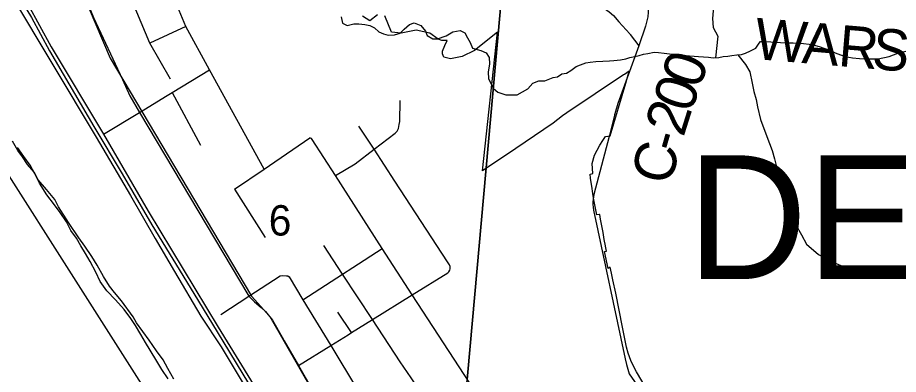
# Model space of a CAD drawing. Extents: x 0 to 43.4, y -8.1 to 22.
# Drawn here: x 3.073 to 4.286, y 17.149 to 17.64 of the extents above; entities that cross this region are included whole.
import ezdxf

# ---------------------------------------------------------------- set-up
doc = ezdxf.new("R2010")
doc.units = 0
for name, color, linetype in [('GM_X_City_Street', 7, 'Continuous'), ('GM_X_Corporation', 7, 'Continuous'), ('GM_X_County_Road', 7, 'Continuous'), ('GM_X_County_Road_Text', 7, 'Continuous'), ('GM_X_Major_River', 7, 'Continuous'), ('GM_X_Minor_River', 7, 'Continuous'), ('GM_X_Rail_Line', 7, 'Continuous'), ('GM_X_Section_Text', 7, 'Continuous'), ('GM_X_Township_Text', 7, 'Continuous'), ('GM_X_US_Route', 7, 'Continuous')]:
    doc.layers.add(name, color=color, linetype=linetype)

msp = doc.modelspace()

# ---------------------------------------------------------------- linework, layer by layer
at = {"layer": 'GM_X_City_Street'}
for p, q in [((3.305, 17.6279), (3.2551, 17.6051)), ((3.286, 17.537), (3.3248, 17.4648)), ((3.3718, 17.4041), (3.4138, 17.3377)), ((3.533, 17.2066), (3.5141, 17.2345))]:
    msp.add_line(p, q, dxfattribs=at)
for points in [[(3.4124, 17.4317), (3.3376, 17.5683), (3.305, 17.6279), (3.2819, 17.6838), (3.2006, 17.8528)], [(3.2836, 17.5556), (3.2551, 17.6051), (3.2315, 17.6623)], [(3.1915, 17.4797), (3.2411, 17.5098), (3.2792, 17.5329), (3.286, 17.537), (3.3376, 17.5683)], [(3.5106, 17.423), (3.538, 17.4391), (3.5639, 17.459), (3.593, 17.4813), (3.5956, 17.4841), (3.5973, 17.4878), (3.5986, 17.4931), (3.5992, 17.4975), (3.5998, 17.5263)], [(3.6688, 17.2965), (3.6685, 17.2977), (3.6675, 17.2999), (3.6651, 17.3041), (3.5926, 17.4152), (3.5639, 17.459), (3.5431, 17.4909)], [(3.3718, 17.4041), (3.4124, 17.4317), (3.4198, 17.4367), (3.4757, 17.4747)], [(3.9415, 16.771), (3.8933, 16.8417), (3.8772, 16.8653), (3.8669, 16.8804), (3.8199, 16.9493), (3.7756, 17.0142), (3.7168, 17.1043), (3.6955, 17.1369), (3.6162, 17.2584), (3.5751, 17.3225), (3.5106, 17.423), (3.4787, 17.4727), (3.4776, 17.4739), (3.4757, 17.4747)], [(3.684, 17.0403), (3.6667, 17.0663), (3.6417, 17.1037), (3.6148, 17.1441), (3.5998, 17.1665), (3.5617, 17.2245), (3.5205, 17.2872), (3.4947, 17.3265)], [(3.466, 17.2519), (3.5205, 17.2872), (3.5345, 17.2963), (3.5751, 17.3225)], [(3.4599, 17.1611), (3.5042, 17.1887), (3.5281, 17.2036), (3.533, 17.2066), (3.5617, 17.2245), (3.6162, 17.2584), (3.6653, 17.289), (3.6669, 17.2904), (3.6681, 17.2924), (3.6687, 17.2946), (3.6688, 17.2965)], [(3.3532, 17.2316), (3.3916, 17.2566), (3.4348, 17.2847), (3.4377, 17.2852), (3.4432, 17.2849)], [(3.4432, 17.2849), (3.4453, 17.2847), (3.4469, 17.2834), (3.466, 17.2519), (3.5042, 17.1887), (3.5412, 17.1277), (3.5791, 17.065), (3.5845, 17.0562), (3.6148, 17.0061), (3.6559, 16.9382), (3.6953, 16.8731), (3.7344, 16.8086)]]:
    msp.add_lwpolyline(points, dxfattribs=at)
at = {"layer": 'GM_X_Corporation'}
for points in [[(8.9, 20.9), (2.1, 20.9), (2.1, 18.7697), (2.2164, 18.6602), (2.3024, 18.5637), (2.4531, 18.3722), (2.5091, 18.2757), (2.5944, 18.1569), (2.6477, 18.0826), (2.8129, 17.7895), (2.9482, 17.5993), (3.2529, 17.1207), (3.3535, 16.9292), (3.4766, 16.7366), (3.5579, 16.6418), (3.619, 16.5459), (3.7774, 16.2543), (3.8686, 16.1561), (3.9643, 16.0791), (4.2564, 15.9373), (4.3533, 15.9108)], [(2.8521, 17.7909), (3.7435, 17.7155), (3.6418, 16.5844)], [(3.5685, 17.644), (3.5579, 17.636), (3.548, 17.6422)], [(3.9385, 17.1301), (3.925, 17.1526), (3.9219, 17.1583), (3.9171, 17.1683), (3.9138, 17.1781), (3.9115, 17.1866), (3.9059, 17.214), (3.8965, 17.2608), (3.8925, 17.2794), (3.8905, 17.2886), (3.8888, 17.2967), (3.886, 17.2949), (3.881, 17.3182), (3.884, 17.3189), (3.8825, 17.3256), (3.8824, 17.3261), (3.8808, 17.3349), (3.8791, 17.3442), (3.8774, 17.3535), (3.8757, 17.3629), (3.8746, 17.3694), (3.8743, 17.3694), (3.8706, 17.3686), (3.8665, 17.3896), (3.8652, 17.3978), (3.8641, 17.4049), (3.8618, 17.4192), (3.8614, 17.4247), (3.8651, 17.4259), (3.8641, 17.4394), (3.8671, 17.4511), (3.8748, 17.4647), (3.8788, 17.471), (3.8823, 17.4767), (3.889, 17.4777), (3.9102, 17.5501), (3.9152, 17.5667), (3.9084, 17.5621), (3.9074, 17.5614), (3.829, 17.509), (3.8233, 17.5051), (3.8102, 17.4951), (3.7588, 17.4603), (3.713, 17.4294), (3.7338, 17.6201), (3.7022, 17.595), (3.685, 17.5869), (3.6689, 17.5838), (3.6598, 17.5857), (3.6582, 17.5903), (3.658, 17.5942), (3.6615, 17.6021), (3.6646, 17.609), (3.6573, 17.6087), (3.6519, 17.6108), (3.6405, 17.6191), (3.6219, 17.6231), (3.6012, 17.6188), (3.5881, 17.6204), (3.5789, 17.6428)], [(2.9482, 17.5993), (3.2529, 17.1207)], [(2.9482, 17.5993), (3.2529, 17.1207)], [(3.2883, 17.1423), (3.2799, 17.1573), (3.2734, 17.1692), (3.2646, 17.1815), (3.2543, 17.1962), (3.2371, 17.2201), (3.2324, 17.2282), (3.2163, 17.2502), (3.2067, 17.2618), (3.1997, 17.2703), (3.1913, 17.2837), (3.1826, 17.2995), (3.1753, 17.3114), (3.1658, 17.3256), (3.1574, 17.3372), (3.1435, 17.3584), (3.1296, 17.3799), (3.1246, 17.3899), (3.1132, 17.4038), (3.1017, 17.417), (3.0959, 17.4277), (3.0867, 17.4382), (3.0798, 17.4486), (3.0735, 17.4574), (3.0663, 17.4701)]]:
    msp.add_lwpolyline(points, dxfattribs=at)
msp.add_lwpolyline([(4.7377, 17.6242), (4.6148, 16.5127), (3.671, 16.5519), (3.6538, 16.5644), (3.6462, 16.5775), (3.6418, 16.5844), (3.7435, 17.7155)], close=True, dxfattribs=at)
at = {"layer": 'GM_X_County_Road'}
for points in [[(3.112, 17.7916), (3.1305, 17.7553), (3.1449, 17.7124), (3.1653, 17.671), (3.1775, 17.6407), (3.2177, 17.5553), (3.2275, 17.5327), (3.2411, 17.5098), (3.3916, 17.2566), (3.3995, 17.2491), (3.4084, 17.2413), (3.4144, 17.2355), (3.424, 17.2239), (3.4374, 17.2005), (3.4403, 17.1954)], [(3.7924, 17.7091), (3.8007, 17.6978), (3.821, 17.6875), (3.8678, 17.6626), (3.8876, 17.6482), (3.8936, 17.6431), (3.901, 17.6346), (3.9158, 17.618)], [(3.9409, 17.6933), (3.9416, 17.6542), (3.9406, 17.6413), (3.9376, 17.6285), (3.9283, 17.6016), (3.8993, 17.522), (3.8953, 17.5077), (3.895, 17.5067)], [(3.9158, 17.618), (3.9165, 17.6172), (3.9283, 17.6016)], [(3.895, 17.5067), (3.8947, 17.5058), (3.8873, 17.4767), (3.8662, 17.3968), (3.8648, 17.3866), (3.8652, 17.3828), (3.8656, 17.3795)], [(3.8656, 17.3795), (3.8661, 17.3752), (3.9094, 17.1706), (3.9115, 17.1626), (3.915, 17.15), (3.9363, 17.1193), (3.9407, 17.113), (3.9477, 17.1015), (3.9526, 17.0854), (3.9596, 17.0599), (3.963, 17.0415), (3.9778, 16.9592), (3.9875, 16.9057), (3.9912, 16.8851)], [(3.4403, 17.1954), (3.4599, 17.1611), (3.4955, 17.099), (3.5317, 17.0357), (3.5663, 16.9762), (3.6066, 16.9068), (3.6432, 16.8438), (3.6835, 16.7745), (3.6969, 16.7515), (3.713, 16.7258), (3.7609, 16.661), (3.7657, 16.655), (3.7823, 16.6344), (3.804, 16.6055), (3.846, 16.5431), (3.887, 16.4854), (3.8904, 16.4807), (3.9025, 16.4638), (3.9229, 16.4395), (3.9444, 16.4189), (3.95, 16.4142), (3.9523, 16.4123)]]:
    msp.add_lwpolyline(points, dxfattribs=at)
at = {"layer": 'GM_X_Major_River'}
msp.add_lwpolyline([(3.2804, 17.1429), (3.2719, 17.1559), (3.2634, 17.1694), (3.2494, 17.1931), (3.2427, 17.2038), (3.2357, 17.2165), (3.229, 17.2261), (3.2201, 17.2384), (3.2078, 17.2515), (3.1959, 17.2642), (3.1869, 17.2769), (3.1807, 17.2899), (3.173, 17.3044), (3.1667, 17.3155), (3.1604, 17.3262), (3.1541, 17.3366), (3.1467, 17.3473), (3.1405, 17.3592), (3.1319, 17.3719), (3.1241, 17.3826), (3.1133, 17.3965), (3.1034, 17.4122), (3.0971, 17.4252), (3.0905, 17.4371), (3.0819, 17.4493), (3.073, 17.4616)], dxfattribs=at)
at = {"layer": 'GM_X_Minor_River'}
for points in [[(4.0741, 17.7643), (4.0698, 17.7511), (4.0666, 17.7413), (4.0636, 17.73), (4.0611, 17.7202), (4.0578, 17.71), (4.0506, 17.6961), (4.0397, 17.6831), (4.0329, 17.6703), (4.0318, 17.6594), (4.0308, 17.6495), (4.0298, 17.6393), (4.0306, 17.6267), (4.0372, 17.6148), (4.0338, 17.5852)], [(3.5187, 17.6413), (3.5204, 17.6329), (3.5269, 17.6297), (3.5361, 17.6318), (3.5429, 17.6317), (3.5513, 17.6308), (3.5582, 17.6296), (3.5646, 17.6264), (3.5706, 17.621), (3.577, 17.6178), (3.5835, 17.6162), (3.5919, 17.6168), (3.5996, 17.6189), (3.6054, 17.6245), (3.6128, 17.6309), (3.6193, 17.6334), (3.6284, 17.6294), (3.6348, 17.6217), (3.637, 17.6156), (3.6449, 17.6113), (3.651, 17.6112), (3.6633, 17.6151), (3.6722, 17.6207), (3.6825, 17.6228), (3.6886, 17.6196), (3.6927, 17.6127), (3.696, 17.6062), (3.6996, 17.5982), (3.711, 17.5949), (3.7182, 17.5917), (3.7223, 17.5856), (3.7229, 17.5768), (3.7208, 17.5651), (3.7214, 17.5567), (3.7251, 17.5487), (3.7284, 17.5429), (3.7344, 17.5375), (3.7454, 17.5342), (3.7527, 17.5341), (3.7607, 17.534), (3.768, 17.538), (3.7754, 17.5425), (3.7824, 17.5503), (3.7908, 17.5532), (3.7989, 17.5534), (3.8104, 17.5578), (3.8162, 17.5588), (3.8223, 17.5629), (3.8288, 17.5639), (3.8346, 17.5676), (3.842, 17.5732), (3.8481, 17.5754), (3.8555, 17.5783), (3.8612, 17.579), (3.8692, 17.5799), (3.8788, 17.5802), (3.888, 17.5808), (3.8941, 17.5814), (3.9033, 17.582), (3.9102, 17.5838), (3.9159, 17.5856), (3.9228, 17.587), (3.9289, 17.588), (3.9347, 17.5898), (3.9405, 17.5909), (3.9493, 17.593), (3.9554, 17.5925), (3.9634, 17.5912), (3.9706, 17.5907), (3.9771, 17.5898), (3.9843, 17.5893), (3.9981, 17.5876), (4.0045, 17.5871), (4.0106, 17.5866), (4.0171, 17.5865), (4.024, 17.586), (4.0308, 17.5851), (4.0385, 17.5853), (4.0442, 17.5867)], [(4.0442, 17.5867), (4.0507, 17.5874), (4.0565, 17.5884), (4.0634, 17.5891), (4.0695, 17.5897), (4.0753, 17.5915), (4.0822, 17.5944), (4.0895, 17.5981), (4.0938, 17.6052), (4.0956, 17.6076)], [(4.0956, 17.6076), (4.1038, 17.6074), (4.1166, 17.6064), (4.1303, 17.6056), (4.1409, 17.6058), (4.1515, 17.6051), (4.1663, 17.6032), (4.1765, 17.6007), (4.1892, 17.5958), (4.2009, 17.591), (4.2125, 17.5869), (4.2224, 17.5851), (4.2322, 17.5841), (4.2451, 17.5834), (4.2576, 17.5835), (4.2729, 17.5869), (4.2848, 17.5912), (4.2958, 17.5943)], [(4.0648, 17.5892), (4.0753, 17.5759), (4.0811, 17.5658), (4.0845, 17.5502), (4.0864, 17.5384), (4.09, 17.5276), (4.0916, 17.5173), (4.0957, 17.5002), (4.1003, 17.4875), (4.1082, 17.4672), (4.1117, 17.4572), (4.1152, 17.4457), (4.118, 17.435), (4.1207, 17.4232), (4.1252, 17.4068), (4.1291, 17.3964), (4.1326, 17.3849), (4.1383, 17.3703), (4.1444, 17.355), (4.152, 17.3411), (4.1589, 17.3284), (4.1756, 17.314), (4.1925, 17.3048), (4.2097, 17.2975), (4.2278, 17.2922), (4.2399, 17.2896), (4.2501, 17.2889), (4.2619, 17.2879), (4.2721, 17.2865), (4.2868, 17.2816)]]:
    msp.add_lwpolyline(points, dxfattribs=at)
at = {"layer": 'GM_X_Rail_Line'}
for points in [[(2.1, 18.9805), (2.1848, 18.9497), (2.3592, 18.8383), (2.5014, 18.7512), (2.6158, 18.6907), (2.7269, 18.6311), (2.7893, 18.6123), (2.8663, 18.5659), (2.9659, 18.5014), (3.0581, 18.4348), (3.118, 18.3921), (3.1299, 18.3321), (3.1312, 18.287), (3.0912, 18.2087), (3.028, 18.1378), (3.0132, 18.0857), (3.0138, 18.043), (3.0154, 18.0122), (3.102, 17.8166), (3.2006, 17.5844), (3.3952, 17.2569), (3.4206, 17.2288), (3.4993, 17.0909)], [(2.4533, 18.5052), (2.6298, 18.3221), (2.6528, 18.2973), (2.6725, 18.2741), (2.6833, 18.2591), (2.6949, 18.2432), (2.7107, 18.2223), (2.7411, 18.181), (2.8345, 18.0491), (2.8879, 17.9734), (2.9104, 17.9401), (2.9307, 17.9086), (2.9591, 17.8611), (3.0063, 17.7808), (3.0709, 17.6763), (3.0924, 17.6406), (3.117, 17.5945), (3.1783, 17.4906), (3.2171, 17.4251), (3.258, 17.3552), (3.3156, 17.2606), (3.348, 17.2078), (3.391, 17.1363)], [(3.0633, 17.6733), (3.1814, 17.4756), (3.2287, 17.3954), (3.2625, 17.3362), (3.2893, 17.2905), (3.3255, 17.2293), (3.3536, 17.1868), (3.3838, 17.1365)]]:
    msp.add_lwpolyline(points, dxfattribs=at)
at = {"layer": 'GM_X_US_Route'}
msp.add_lwpolyline([(2.8233, 18.2456), (2.8261, 18.2362), (2.8285, 18.2267), (2.8311, 18.2164), (2.8524, 18.1326), (2.8706, 18.0673), (2.8904, 18.0216), (2.9182, 17.9652), (2.9532, 17.9024), (2.9747, 17.8697), (3.0247, 17.7876), (3.0554, 17.7181), (3.1193, 17.6002), (3.1915, 17.4797), (3.253, 17.3737), (3.3492, 17.2141), (3.4666, 17.0224)], dxfattribs=at)

# ---------------------------------------------------------------- texts
at = {"layer": 'GM_X_County_Road_Text'}
for s, rotation, p in [('W', 355.2095, (4.0861, 17.5835)), ('A', 355.2078, (4.1517, 17.578)), ('R', 355.2074, (4.2015, 17.5738)), ('S', 355.1907, (4.248, 17.5699)), ('0', 70.4941, (4.0114, 17.5406)), ('0', 71.0018, (4, 17.5076)), ('2', 72.4731, (3.9896, 17.4746)), ('-', 73.8712, (3.9832, 17.4526)), ('C', 75.6192, (3.9718, 17.4078))]:
    msp.add_text(s, height=0.0568, rotation=rotation, dxfattribs=at).set_placement(p)
at = {"layer": 'GM_X_Section_Text'}
msp.add_text('6', height=0.0419, rotation=0, dxfattribs=at).set_placement((3.4189, 17.3402))
at = {"layer": 'GM_X_Township_Text'}
msp.add_text('DELHI', height=0.17045, rotation=0, dxfattribs=at).set_placement((3.9954, 17.2803))

doc.saveas('drawing.dxf')
